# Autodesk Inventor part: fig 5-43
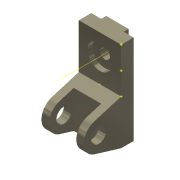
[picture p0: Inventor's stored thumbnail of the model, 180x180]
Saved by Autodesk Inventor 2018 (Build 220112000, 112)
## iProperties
Shininess: 65.0
Angle Display Precision: 2
Document Length Units: 11269
Document Angle Units: 11279
Document Time Units: 11290
Document Mass Units: 11283
Document Length Units Precision: 3
Document Angle Units Precision: 2
Created: 2001-11
Part Number: fig 5-43
Document SubType Name: Modeling
Designer: Renu Muthoo
Density: 1 g/cm^3
Material: Generic
Appearance: Metal-Titanium (Polished)
Density: 0.0
Volumn: 0.0
Area: 0.0
PropertySet Name: Model Information
Control State: 0
Master: False
Checked Out: False
Author: Renu Muthoo
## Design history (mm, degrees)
node "Sketch1"
sketch "Sketch2"
  geometry: L1 (33.257, 104.664)-(33.257, -75.336); L2 (33.257, -75.336)-(8.257, -75.336); L3 (8.257, -75.336)-(-45.451, -59.045); L4 (-45.451, -1.628)-(8.257, 14.664); L5 (8.257, 14.664)-(8.257, 104.664); L6 (8.257, 104.664)-(33.257, 104.664); C1 r 15 at (-36.743, -30.336); A1 r 30 centre (-36.743, -30.336) between (-45.451, -1.628) and (-45.451, -59.045)
  constraints: 12 end point, 2 centre point, 2 equal length, 2 parallel, 2 point on circle, 2 tangent, 1 coincident, 1 perpendicular, 1 vertical
  dimensions: "d0" = 180 distance of L1.start L1.end; "d1" = 30 radius of A1; "d2" = 25 distance of L5.end L1.start; "d3" = 45 distance from line of L2 A1.centre; "d4" = 70 distance from line of L1 A1.centre; "d5" = 30 diameter of C1
extrude "Extrusion1" new body sketch "Sketch2" distance "d6" = 85; taper "d7" = 0 deg
workplane "Work Plane1"
sketch "Sketch3"
  geometry: L1 (15, 62.364)-(70, 62.364); L2 (70, 62.364)-(70, -52.386); L3 (70, -52.386)-(15, -52.386); L4 (15, -52.386)-(15, 62.364); L5 (0, -45)-(0, -28.708) reference
  constraints: 8 end point, 2 parallel, 1 horizontal, 1 perpendicular
  dimensions: "d8" = 55 distance of L1.start L1.end; "d9" = 15 distance between parallel lines of L5 L4
extrude "Extrusion2" cut sketch "Sketch3" distance "d10" = 50; taper "d11" = 0 deg
sketch "Sketch4"
  geometry: L1 (0, 25)-(85, 25) reference; L2 (0, 0)-(0, 25) reference; L3 (20, 25)-(65, 25); L4 (65, 25)-(65, 35); L5 (65, 35)-(20, 35); L6 (20, 35)-(20, 25)
  constraints: 8 end point, 2 parallel, 1 horizontal, 1 perpendicular, 1 point on line
  dimensions: "d12" = 45 distance of L4.end L5.end; "d13" = 10 distance of L3.end L4.end; "d14" = 20 distance between parallel lines of L2 L6
extrude "Extrusion3" join sketch "Sketch4" stored distance "d15" = 50; taper "d16" = 0 deg
sketch "Sketch5"
  geometry: L1 (85, 0)-(85, 90) reference; L2 (0, 90)-(85, 90) reference; 1 further point
  dimensions: "d17" = 42 distance from line of L2 point (42.5, 48); "d18" = 42.5 distance from line of L1 point (42.5, 48)
hole "Hole1" sketch "Sketch5" at (42.5, 48) diameter "d19" = 20; stored, may be unused: countersink angle "d23" = 82 deg, drill point angle "d25" = 118 deg; dims "d20" = 6, "d21" = 50, "d22" = 10, "d24" = 8
workpoint "Work Point1"
workpoint "Work Point2"
workpoint "Work Point3"
workpoint "Work Point4"
workaxis "Work Axis2"
body "Solid1"
